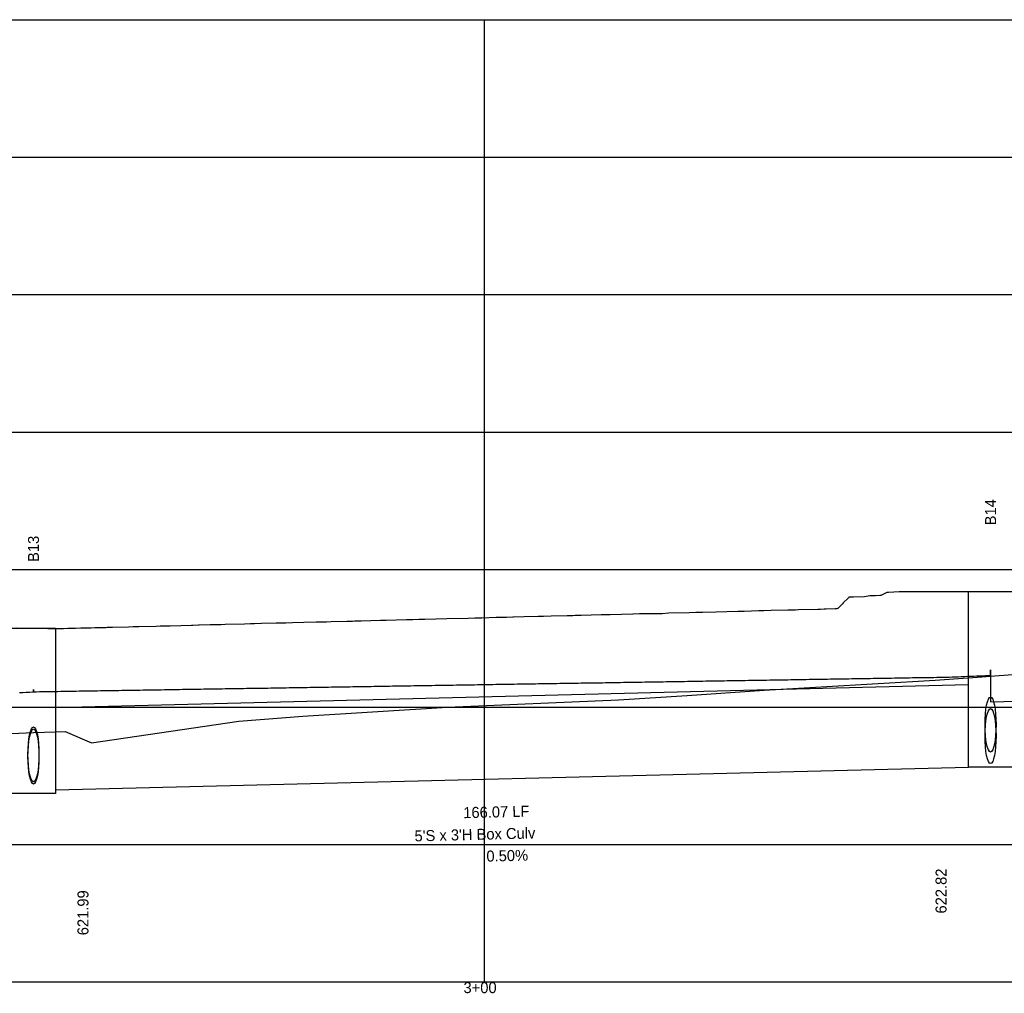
# Model space of a CAD drawing. Extents: x 2253035 to 2279930, y 13774972 to 13793443.
# Drawn here: x 2260241.9 to 2260421, y 13791296.5 to 13791473.6 of the extents above; entities that cross this region are included whole.
import ezdxf

# ---------------------------------------------------------------- set-up
doc = ezdxf.new("R2010")
doc.units = 0
for name, color, linetype in [('Default', 7, 'Continuous'), ('E_Utility_ATT_HH', 7, 'Continuous'), ('E_Utility_ATT_PR_PVC', 7, 'Continuous'), ('E_Utillity_Water_Water Line_12in', 7, 'Continuous'), ('E_Utillity_Water_Water Line_1in', 7, 'Continuous'), ('E_Utillity_Water_Water Line_4in', 7, 'Continuous'), ('E_Utillity_Water_Water Line_8in', 7, 'Continuous')]:
    doc.layers.add(name, color=color, linetype=linetype)

msp = doc.modelspace()

# ---------------------------------------------------------------- linework, layer by layer
at = {"layer": 'Default'}
for p, q in [((2260326.46, 13791298.56), (2260326.46, 13791473.56)), ((2260026.46, 13791448.56), (2261320.64, 13791448.56)), ((2260026.46, 13791423.56), (2261320.64, 13791423.56)), ((2260026.46, 13791398.56), (2261320.64, 13791398.56)), ((2260026.46, 13791373.56), (2261320.64, 13791373.56)), ((2260026.46, 13791348.56), (2261320.64, 13791348.56)), ((2260026.46, 13791323.56), (2261320.64, 13791323.56))]:
    msp.add_line(p, q, dxfattribs=at)
msp.add_lwpolyline([(2260026.46, 13791298.56), (2260026.46, 13791473.56), (2261320.64, 13791473.56), (2261320.64, 13791298.56)], close=True, dxfattribs=at)
at = {"layer": 'E_Utility_ATT_PR_PVC'}
for p, q in [((2260418.51, 13791355.36), (2260418.51, 13791349.55)), ((2260244.44, 13791351.76), (2260244.44, 13791351.36))]:
    msp.add_line(p, q, dxfattribs=at)
for points in [[(2260244.44, 13791351.36), (2260245, 13791351.37), (2260245.55, 13791351.38), (2260246.1, 13791351.39), (2260246.66, 13791351.4), (2260247.21, 13791351.41), (2260247.76, 13791351.42), (2260248.32, 13791351.42), (2260248.87, 13791351.43), (2260249.42, 13791351.44), (2260249.98, 13791351.45), (2260250.53, 13791351.46), (2260251.08, 13791351.47), (2260251.64, 13791351.48), (2260252.19, 13791351.49), (2260252.74, 13791351.5), (2260253.3, 13791351.5), (2260253.85, 13791351.51), (2260254.4, 13791351.52), (2260254.96, 13791351.53), (2260255.51, 13791351.54), (2260256.06, 13791351.55), (2260256.62, 13791351.56), (2260257.17, 13791351.57), (2260257.72, 13791351.58), (2260258.28, 13791351.58), (2260258.83, 13791351.59), (2260259.38, 13791351.6), (2260259.94, 13791351.61), (2260260.49, 13791351.62), (2260261.04, 13791351.63), (2260261.6, 13791351.64), (2260262.15, 13791351.65), (2260262.7, 13791351.65), (2260263.26, 13791351.66), (2260263.81, 13791351.67), (2260264.36, 13791351.68), (2260264.92, 13791351.69), (2260265.47, 13791351.7), (2260266.02, 13791351.71), (2260266.58, 13791351.72), (2260267.13, 13791351.73), (2260267.68, 13791351.73), (2260268.24, 13791351.74), (2260268.79, 13791351.75), (2260269.34, 13791351.76), (2260269.9, 13791351.77), (2260270.45, 13791351.78), (2260271, 13791351.79), (2260271.55, 13791351.8), (2260272.11, 13791351.8), (2260272.66, 13791351.81), (2260273.21, 13791351.82), (2260273.77, 13791351.83), (2260274.32, 13791351.84), (2260274.87, 13791351.85), (2260275.43, 13791351.86), (2260275.98, 13791351.87), (2260276.53, 13791351.88), (2260277.09, 13791351.88), (2260277.64, 13791351.89), (2260278.19, 13791351.9), (2260278.75, 13791351.91), (2260279.3, 13791351.92), (2260279.85, 13791351.93), (2260280.41, 13791351.94), (2260280.96, 13791351.95), (2260281.51, 13791351.95), (2260282.07, 13791351.96), (2260282.62, 13791351.97), (2260283.17, 13791351.98), (2260283.73, 13791351.99), (2260284.28, 13791352), (2260284.83, 13791352.01), (2260285.39, 13791352.02), (2260285.94, 13791352.03), (2260286.49, 13791352.03), (2260287.05, 13791352.04), (2260287.6, 13791352.05), (2260288.15, 13791352.06), (2260288.71, 13791352.07), (2260289.26, 13791352.08), (2260289.81, 13791352.09), (2260290.37, 13791352.1), (2260290.92, 13791352.11), (2260291.47, 13791352.11), (2260292.03, 13791352.12), (2260292.58, 13791352.13), (2260293.13, 13791352.14), (2260293.69, 13791352.15), (2260294.24, 13791352.16), (2260294.79, 13791352.17), (2260295.35, 13791352.18), (2260295.9, 13791352.18), (2260296.45, 13791352.19), (2260297.01, 13791352.2), (2260297.56, 13791352.21), (2260298.11, 13791352.22), (2260298.67, 13791352.23), (2260299.22, 13791352.24), (2260299.77, 13791352.25), (2260300.33, 13791352.26), (2260300.88, 13791352.26), (2260301.43, 13791352.27), (2260301.98, 13791352.28), (2260302.54, 13791352.29), (2260303.09, 13791352.3), (2260303.64, 13791352.31), (2260304.2, 13791352.32), (2260304.75, 13791352.33), (2260305.3, 13791352.33), (2260305.86, 13791352.34), (2260306.41, 13791352.35), (2260306.96, 13791352.36), (2260307.52, 13791352.37), (2260308.07, 13791352.38), (2260308.62, 13791352.39), (2260309.18, 13791352.4), (2260309.73, 13791352.41), (2260310.28, 13791352.41), (2260310.84, 13791352.42), (2260311.39, 13791352.43), (2260311.94, 13791352.44), (2260312.5, 13791352.45), (2260313.05, 13791352.46), (2260313.6, 13791352.47), (2260314.16, 13791352.48), (2260314.71, 13791352.48), (2260315.26, 13791352.49), (2260315.82, 13791352.5), (2260316.37, 13791352.51), (2260316.92, 13791352.52), (2260317.48, 13791352.53), (2260318.03, 13791352.54), (2260318.58, 13791352.55), (2260319.14, 13791352.56), (2260319.69, 13791352.56), (2260320.24, 13791352.57), (2260320.8, 13791352.58), (2260321.35, 13791352.59), (2260321.9, 13791352.6), (2260322.46, 13791352.61), (2260323.01, 13791352.62), (2260323.56, 13791352.63), (2260324.12, 13791352.63), (2260324.67, 13791352.64), (2260325.22, 13791352.65), (2260325.78, 13791352.66), (2260326.33, 13791352.67), (2260326.88, 13791352.68), (2260327.44, 13791352.69), (2260327.99, 13791352.7), (2260328.54, 13791352.71), (2260329.1, 13791352.71), (2260329.65, 13791352.72), (2260330.2, 13791352.73), (2260330.76, 13791352.74), (2260331.31, 13791352.75), (2260331.86, 13791352.76), (2260332.41, 13791352.77), (2260332.97, 13791352.78), (2260333.52, 13791352.79), (2260334.07, 13791352.79), (2260334.63, 13791352.8), (2260335.18, 13791352.81), (2260335.73, 13791352.82), (2260336.29, 13791352.83), (2260336.84, 13791352.84), (2260337.39, 13791352.85), (2260337.95, 13791352.86), (2260338.5, 13791352.86), (2260339.05, 13791352.87), (2260339.61, 13791352.88), (2260340.16, 13791352.89), (2260340.71, 13791352.9), (2260341.27, 13791352.91), (2260341.82, 13791352.92), (2260342.37, 13791352.93), (2260342.93, 13791352.94), (2260343.48, 13791352.94), (2260344.03, 13791352.95), (2260344.59, 13791352.96), (2260345.14, 13791352.97), (2260345.69, 13791352.98), (2260346.25, 13791352.99), (2260346.8, 13791353), (2260347.35, 13791353.01), (2260347.91, 13791353.01), (2260348.46, 13791353.02), (2260349.01, 13791353.03), (2260349.57, 13791353.04), (2260350.12, 13791353.05), (2260350.67, 13791353.06), (2260351.23, 13791353.07), (2260351.78, 13791353.08), (2260352.33, 13791353.09), (2260352.89, 13791353.09), (2260353.44, 13791353.1), (2260353.99, 13791353.11), (2260354.55, 13791353.12), (2260355.1, 13791353.13), (2260355.65, 13791353.14), (2260356.21, 13791353.15), (2260356.76, 13791353.16), (2260357.31, 13791353.16), (2260357.87, 13791353.17), (2260358.42, 13791353.18), (2260358.97, 13791353.19), (2260359.53, 13791353.2), (2260360.08, 13791353.21), (2260360.63, 13791353.22), (2260361.19, 13791353.23), (2260361.74, 13791353.24), (2260362.29, 13791353.24), (2260362.85, 13791353.25), (2260363.4, 13791353.26), (2260363.95, 13791353.27), (2260364.5, 13791353.28), (2260365.06, 13791353.29), (2260365.61, 13791353.3), (2260366.16, 13791353.31), (2260366.72, 13791353.32), (2260367.27, 13791353.32), (2260367.82, 13791353.33), (2260368.38, 13791353.34), (2260368.93, 13791353.35), (2260369.48, 13791353.36), (2260370.04, 13791353.37), (2260370.59, 13791353.38), (2260371.14, 13791353.39), (2260371.7, 13791353.39), (2260372.25, 13791353.4), (2260372.8, 13791353.41), (2260373.36, 13791353.42), (2260373.91, 13791353.43), (2260374.46, 13791353.44), (2260375.02, 13791353.45), (2260375.57, 13791353.46), (2260376.12, 13791353.47), (2260376.68, 13791353.47), (2260377.23, 13791353.48), (2260377.78, 13791353.49), (2260378.34, 13791353.5), (2260378.89, 13791353.51), (2260379.44, 13791353.52), (2260380, 13791353.53), (2260380.55, 13791353.54), (2260381.1, 13791353.54), (2260381.66, 13791353.55), (2260382.21, 13791353.56), (2260382.76, 13791353.57), (2260383.32, 13791353.58), (2260383.87, 13791353.59), (2260384.42, 13791353.6), (2260384.98, 13791353.61), (2260385.53, 13791353.62), (2260386.08, 13791353.62), (2260386.64, 13791353.63), (2260387.19, 13791353.64), (2260387.74, 13791353.65), (2260388.3, 13791353.66), (2260388.85, 13791353.67), (2260389.4, 13791353.68), (2260389.96, 13791353.69), (2260390.51, 13791353.69), (2260391.06, 13791353.7), (2260391.62, 13791353.71), (2260392.17, 13791353.72), (2260392.72, 13791353.73), (2260393.28, 13791353.74), (2260393.83, 13791353.75), (2260394.38, 13791353.76), (2260394.93, 13791353.77), (2260395.49, 13791353.77), (2260396.04, 13791353.78), (2260396.59, 13791353.79), (2260397.15, 13791353.8), (2260397.7, 13791353.81), (2260398.25, 13791353.82), (2260398.81, 13791353.83), (2260399.36, 13791353.84), (2260399.91, 13791353.84), (2260400.47, 13791353.85), (2260401.02, 13791353.86), (2260401.57, 13791353.87), (2260402.13, 13791353.88), (2260402.68, 13791353.89), (2260403.23, 13791353.9), (2260403.79, 13791353.91), (2260404.34, 13791353.92), (2260404.89, 13791353.92), (2260405.45, 13791353.93), (2260406, 13791353.94), (2260406.55, 13791353.95), (2260407.11, 13791353.96), (2260407.66, 13791353.97), (2260408.21, 13791353.98), (2260408.77, 13791353.99), (2260409.32, 13791354), (2260409.87, 13791354), (2260410.43, 13791354.01), (2260410.98, 13791354.03), (2260411.53, 13791354.06), (2260412.09, 13791354.08), (2260412.64, 13791354.1), (2260413.19, 13791354.12), (2260413.75, 13791354.15), (2260414.3, 13791354.17), (2260414.85, 13791354.19), (2260415.41, 13791354.21), (2260415.96, 13791354.24), (2260416.51, 13791354.26), (2260417.07, 13791354.28), (2260417.62, 13791354.31), (2260418.17, 13791354.33), (2260418.51, 13791354.34), (2260418.51, 13791355.36)], [(2260418.51, 13791349.55), (2260577.85, 13791353.53)], [(2260241.92, 13791351.23), (2260242.51, 13791351.25), (2260243.1, 13791351.28), (2260243.7, 13791351.3), (2260244.29, 13791351.33), (2260244.44, 13791351.33), (2260244.44, 13791351.76)]]:
    msp.add_lwpolyline(points, dxfattribs=at)
at = {"layer": 'E_Utillity_Water_Water Line_12in'}
for points in [[(2260414.51, 13791369.59), (2260422.51, 13791369.59), (2260422.51, 13791337.66), (2260414.51, 13791337.66)], [(2260240.44, 13791362.93), (2260248.44, 13791362.93), (2260248.44, 13791332.86), (2260240.44, 13791332.86)]]:
    msp.add_lwpolyline(points, close=True, dxfattribs=at)
at = {"layer": 'E_Utillity_Water_Water Line_1in'}
msp.add_lwpolyline([(2260240.44, 13791343.79), (2260244.44, 13791343.93), (2260244.44, 13791343.93), (2260248.44, 13791344.07), (2260248.44, 13791344.07), (2260250.19, 13791344.14), (2260254.96, 13791342.09), (2260281.77, 13791346.03), (2260293.4, 13791346.92), (2260319.75, 13791348.56), (2260350.86, 13791349.9), (2260363.32, 13791350.7), (2260377.31, 13791351.64), (2260408.42, 13791353.47), (2260414.35, 13791353.86), (2260414.51, 13791353.88), (2260414.51, 13791353.88), (2260418.51, 13791354.19), (2260418.51, 13791354.19), (2260422.51, 13791354.51)], dxfattribs=at)
at = {"layer": 'E_Utillity_Water_Water Line_4in'}
for p, q in [((2260248.44, 13791348.5), (2260414.51, 13791352.66)), ((2260248.44, 13791333.5), (2260414.51, 13791337.66))]:
    msp.add_line(p, q, dxfattribs=at)
for centre in [(2260418.51, 13791345.39), (2260418.51, 13791343.3), (2260244.44, 13791339.98), (2260244.44, 13791339.58)]:
    msp.add_ellipse(centre, major_axis=(0, 5), ratio=0.2, dxfattribs=at)
at = {"layer": 'E_Utillity_Water_Water Line_8in'}
msp.add_lwpolyline([(2260241.36, 13791363), (2260243.52, 13791362.95), (2260244.44, 13791362.93), (2260244.44, 13791362.93), (2260244.61, 13791362.93), (2260244.69, 13791362.93), (2260244.75, 13791362.93), (2260247.06, 13791362.87), (2260248.44, 13791362.84), (2260248.44, 13791362.84), (2260248.59, 13791362.84), (2260249.08, 13791362.85), (2260249.09, 13791362.85), (2260249.1, 13791362.85), (2260249.88, 13791362.87), (2260250.7, 13791362.9), (2260251.09, 13791362.91), (2260251.1, 13791362.91), (2260251.66, 13791362.92), (2260251.95, 13791362.93), (2260252.01, 13791362.93), (2260252.02, 13791362.93), (2260252.07, 13791362.93), (2260253.08, 13791362.96), (2260253.25, 13791362.96), (2260254.52, 13791362.99), (2260254.83, 13791363), (2260254.89, 13791363), (2260254.93, 13791363), (2260255.57, 13791363.02), (2260255.64, 13791363.02), (2260256.61, 13791363.05), (2260257.62, 13791363.07), (2260257.85, 13791363.08), (2260258.25, 13791363.09), (2260258.83, 13791363.1), (2260261.69, 13791363.18), (2260262.56, 13791363.2), (2260263.6, 13791363.23), (2260266.76, 13791363.31), (2260267.46, 13791363.32), (2260268.09, 13791363.34), (2260268.81, 13791363.36), (2260269.28, 13791363.37), (2260273.16, 13791363.47), (2260273.4, 13791363.48), (2260274.46, 13791363.5), (2260274.6, 13791363.51), (2260276.55, 13791363.56), (2260278.55, 13791363.56), (2260278.6, 13791363.56), (2260279.29, 13791363.63), (2260282.81, 13791363.72), (2260283.93, 13791363.75), (2260283.93, 13791363.75), (2260283.94, 13791363.75), (2260284.42, 13791363.76), (2260284.61, 13791363.76), (2260285.89, 13791363.8), (2260285.92, 13791363.8), (2260285.92, 13791363.8), (2260288.6, 13791363.86), (2260290.36, 13791363.91), (2260291.55, 13791363.94), (2260293.6, 13791363.99), (2260295.88, 13791364.05), (2260297.48, 13791364.09), (2260297.71, 13791364.1), (2260298.6, 13791364.12), (2260301.41, 13791364.19), (2260302.49, 13791364.22), (2260302.9, 13791364.23), (2260303.36, 13791364.24), (2260304.04, 13791364.26), (2260307.57, 13791364.35), (2260308.08, 13791364.36), (2260308.6, 13791364.38), (2260312.28, 13791364.47), (2260312.5, 13791364.48), (2260313.46, 13791364.5), (2260314.55, 13791364.53), (2260314.62, 13791364.53), (2260315.61, 13791364.56), (2260319.61, 13791364.66), (2260323.5, 13791364.76), (2260324.74, 13791364.79), (2260325.98, 13791364.82), (2260326.01, 13791364.82), (2260326.01, 13791364.82), (2260328.6, 13791364.89), (2260330.5, 13791364.94), (2260331.64, 13791364.97), (2260331.74, 13791364.97), (2260333.7, 13791365.02), (2260336.24, 13791365.08), (2260337.21, 13791365.11), (2260338.6, 13791365.14), (2260341.52, 13791365.22), (2260342.53, 13791365.25), (2260342.96, 13791365.26), (2260343.43, 13791365.27), (2260344.06, 13791365.28), (2260347.7, 13791365.38), (2260348.15, 13791365.39), (2260348.92, 13791365.41), (2260349.33, 13791365.42), (2260353.44, 13791365.52), (2260353.52, 13791365.53), (2260354.65, 13791365.56), (2260354.65, 13791365.56), (2260354.68, 13791365.56), (2260358.37, 13791365.56), (2260358.76, 13791365.56), (2260359.93, 13791365.69), (2260363.68, 13791365.79), (2260364.88, 13791365.82), (2260366.07, 13791365.85), (2260366.1, 13791365.85), (2260368.6, 13791365.91), (2260370.55, 13791365.96), (2260372.56, 13791366.01), (2260372.65, 13791366.02), (2260372.76, 13791366.02), (2260373.7, 13791366.04), (2260376.37, 13791366.11), (2260377.29, 13791366.14), (2260378.6, 13791366.17), (2260381.64, 13791366.25), (2260382.57, 13791366.27), (2260383.01, 13791366.28), (2260383.6, 13791366.3), (2260387.1, 13791366.39), (2260387.57, 13791366.4), (2260388.27, 13791366.42), (2260388.58, 13791366.42), (2260390.24, 13791366.47), (2260390.62, 13791366.52), (2260390.74, 13791366.55), (2260390.8, 13791366.56), (2260391.63, 13791367.4), (2260391.69, 13791367.41), (2260391.78, 13791367.56), (2260392.56, 13791368.34), (2260392.77, 13791368.56), (2260392.82, 13791368.6), (2260393.6, 13791368.64), (2260395.59, 13791368.66), (2260396.56, 13791368.86), (2260397.25, 13791368.87), (2260397.61, 13791368.88), (2260398.36, 13791368.89), (2260398.49, 13791368.9), (2260398.6, 13791368.94), (2260399.7, 13791369.45), (2260399.77, 13791369.45), (2260399.81, 13791369.45), (2260399.88, 13791369.46), (2260399.95, 13791369.46), (2260401.92, 13791369.56), (2260403.41, 13791369.56), (2260403.64, 13791369.56), (2260405.84, 13791369.56), (2260405.88, 13791369.56), (2260408.18, 13791369.57), (2260408.69, 13791369.57), (2260410.74, 13791369.57), (2260412.85, 13791369.58), (2260413.63, 13791369.58), (2260414.51, 13791369.58), (2260414.51, 13791369.58), (2260414.52, 13791369.58), (2260417, 13791369.58), (2260417.11, 13791369.59), (2260417.25, 13791369.59), (2260418.51, 13791369.59), (2260418.51, 13791369.59), (2260418.6, 13791369.59), (2260418.63, 13791369.59), (2260419.82, 13791369.59), (2260420, 13791369.6), (2260422.51, 13791369.61)], dxfattribs=at)

# ---------------------------------------------------------------- texts
at = {"layer": 'Default'}
msp.add_text('3+00', height=2, dxfattribs=at).set_placement((2260322.65, 13791296.56))
at = {"layer": 'E_Utility_ATT_HH'}
for s, rotation, p in [('B14', 90, (2260419.51, 13791381.62)), ('B13', 90, (2260245.44, 13791374.96)), ('166.07 LF', 1.4321, (2260322.63, 13791328.36)), ("5'S x 3'H Box Culv", 1.4321, (2260313.77, 13791324.14)), ('0.50%', 1.4321, (2260326.84, 13791320.46)), ('622.82', 90, (2260410.51, 13791311.03)), ('621.99', 90, (2260254.44, 13791307.08))]:
    msp.add_text(s, height=2, rotation=rotation, dxfattribs=at).set_placement(p)

doc.saveas('drawing.dxf')
